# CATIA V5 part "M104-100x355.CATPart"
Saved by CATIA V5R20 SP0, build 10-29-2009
Part number: M104-100x355
Source: Unknown
Bounding box of the stored display mesh (mm): x -49.986 to 49.986, y -49.986 to 49.986, z 0 to 355
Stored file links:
  C:\Users\Utente\Desktop\IO LAVORO\3D X SITO CF\X SITO\M104\M104-100x355.CATPart
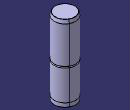
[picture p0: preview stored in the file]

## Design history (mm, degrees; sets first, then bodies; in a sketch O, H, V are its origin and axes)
Body1 (main body)
  Solid1 "PartBody": solid without history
